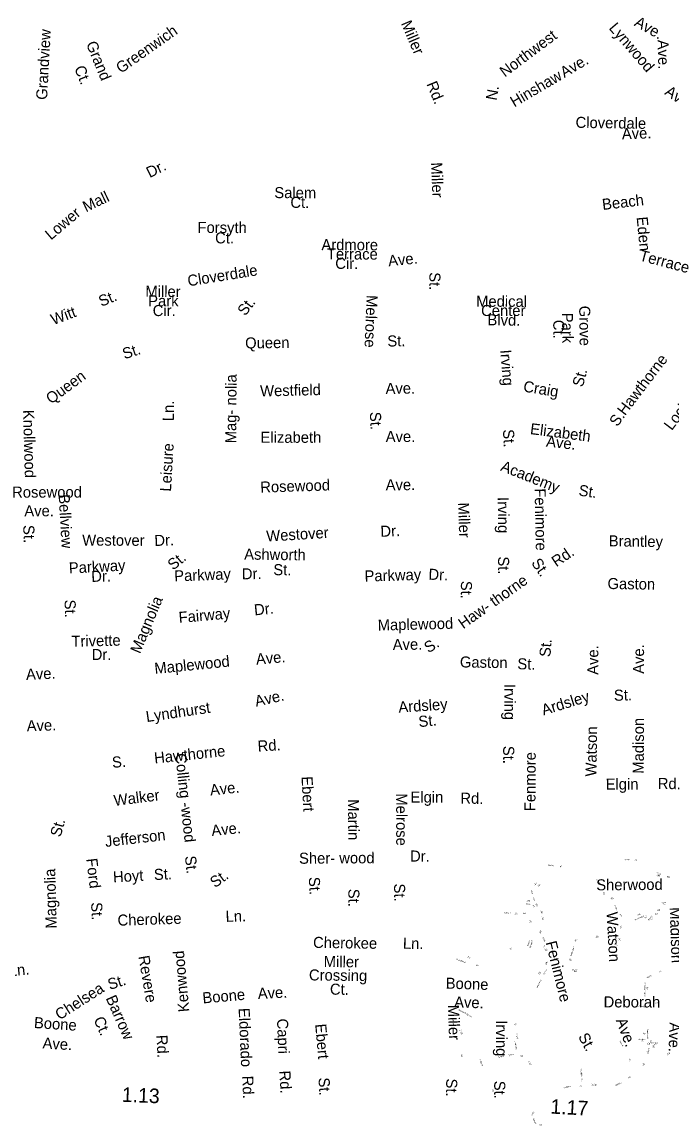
# Model space of a CAD drawing. Extents: x 1553981 to 1780076, y 812965 to 996873.
# Drawn here: x 1620006 to 1625598, y 846729 to 856224 of the extents above; entities that cross this region are included whole.
import ezdxf

# ---------------------------------------------------------------- set-up
doc = ezdxf.new("R2010")
doc.units = 0
for name, color, linetype in [('Exist Road Non-System Type 51 Label', 7, 'Continuous'), ('Exist Road Primary NC Service Mileage Hundredths English Label', 7, 'Continuous'), ('Exist Road Secondary Mileage Hundredths English Label', 7, 'Continuous'), ('Map Preparation Border Antique Large Shape', 7, 'Continuous')]:
    doc.layers.add(name, color=color, linetype=linetype)

msp = doc.modelspace()

# ---------------------------------------------------------------- texts
at = {"layer": 'Exist Road Non-System Type 51 Label'}
for s, height, rotation, p in [('Greenwich', 95, 35.10708, (1620857, 855778.8)), ('Miller', 95, 293.05731, (1623265.4, 856213.3)), ('Lynwood', 95, 310.80779, (1625050.9, 856169.5)), ('Ave.', 95, 330.70891, (1625267.3, 856196.5)), ('Grandview', 95, 86.90435, (1620221.3, 855553.6)), ('Northwest', 95, 36.8499, (1624160.7, 855746.1)), ('Grand', 95, 292.26871, (1620555.3, 856037.4)), ('Ave.', 95, 271.79659, (1625474.2, 856070.7)), ('Ave.', 95, 30.68947, (1624672.3, 855741.7)), ('Ct.', 95, 292.26871, (1620453.7, 855827.4)), ('Rd.', 95, 292.38447, (1623484.6, 855691.5)), ('Hinshaw', 95, 30.38797, (1624241.9, 855489.3)), ('N.', 95, 79.68363, (1624089.3, 855545.4)), ('Ave.', 95, 325.83454, (1625529, 855605.9)), ('Cloverdale', 95, 359.11757, (1624768.8, 855314.4)), ('Ave.', 95, 2.09329, (1625169.2, 855215.2)), ('Dr.', 95, 26.54378, (1621105.3, 854881.2)), ('Miller', 95, 272.09378, (1623526, 855016)), ('Mall', 95, 25.69886, (1620556.5, 854586.8)), ('Salem', 95, 359.76311, (1622177.1, 854709.8)), ('Ct.', 95, 359.76311, (1622315.1, 854625.8)), ('Beach', 95, 6.73645, (1625003.3, 854607.3)), ('Lower', 95, 40.10596, (1620254.4, 854344.2)), ('Forsyth', 95, 359.76311, (1621516.2, 854410.4)), ('Eden', 95, 275.42573, (1625294.4, 854545.6)), ('Ct.', 95, 359.76311, (1621667.2, 854320.3)), ('Ardmore', 95, 359.76311, (1622582.3, 854262)), ('Terrace', 95, 359.76311, (1622629.4, 854182.5)), ('Cir.', 95, 359.76311, (1622701.3, 854101.1)), ('Ave.', 95, 5.53498, (1623160.9, 854123.1)), ('Terrace', 95, 345.23935, (1625311.7, 854174.5)), ('Cloverdale', 95, 9.13157, (1621438.1, 853950.3)), ('St.', 95, 269.36723, (1623511.9, 854072.6)), ('Miller', 95, 359.25494, (1621066.9, 853861.8)), ('St.', 95, 22.14844, (1620688.4, 853774)), ('Park', 95, 359.97373, (1621091.9, 853778.5)), ('St.', 95, 52.13116, (1621925.7, 853690.3)), ('Melrose', 95, 267.67239, (1622971.4, 853877)), ('Medical', 95, 359.87892, (1623913.5, 853775.2)), ('Witt', 95, 20.39681, (1620275.3, 853616.5)), ('Cir.', 95, 0.04818, (1621130.5, 853694.9)), ('Center', 95, 0.0174, (1623956.5, 853695.6)), ('Blvd.', 95, 358.93461, (1624010.7, 853616.4)), ('Park', 95, 270.7268, (1624651.6, 853722.6)), ('Grove', 95, 270.7268, (1624800.2, 853783.7)), ('Ct.', 95, 270.7268, (1624576.5, 853662.4)), ('St.', 95, 1.58406, (1623150.8, 853432.2)), ('St.', 95, 18.38724, (1620888, 853322.3)), ('Queen', 95, 0.76734, (1621926.5, 853415.9)), ('Irving', 95, 274.44308, (1624120.9, 853402.3)), ('Hawthorne', 95, 52.62576, (1625194.5, 852833.3)), ('Queen', 95, 36.1182, (1620255.7, 852934.3)), ('Mag- nolia', 95, 89.70477, (1621849.2, 852600.7)), ('St.', 95, 74.54113, (1624830.9, 853079.5)), ('Lockland', 95, 52.93573, (1625596.8, 852705.3)), ('Westfield', 95, 1.36967, (1622056, 853003.1)), ('Ave.', 95, 0.8492, (1623135, 853024.9)), ('Craig', 95, 350.84398, (1624314.9, 853046.3)), ('Ln.', 95, 89.09124, (1621312.1, 852790.4)), ('Knollwood', 95, 271.55283, (1620014.8, 852887.2)), ('St.', 95, 272.30603, (1622999.2, 852869.3)), ('Elizabeth', 95, 352.6529, (1624374.3, 852680.5)), ('S.', 95, 53.98185, (1625128.5, 852738)), ('Elizabeth', 95, 0.02895, (1622058.6, 852604.7)), ('Ave.', 95, 359.99417, (1623135.7, 852612)), ('St.', 95, 273.23632, (1624143.8, 852719)), ('Leisure', 95, 86.7488, (1621287.9, 852183.3)), ('Ave.', 95, 353.64895, (1624512.8, 852572.9)), ('Academy', 95, 338.24252, (1624116.7, 852367.6)), ('Rosewood', 95, 1.86335, (1622057.5, 852176.1)), ('Ave.', 95, 0.30163, (1623135.5, 852196.5)), ('Rosewood', 95, 0.03651, (1619921, 852133.4)), ('Fenimore', 95, 271.14432, (1624416.8, 852212.4)), ('St.', 95, 351.40585, (1624791, 852152.1)), ('Bellview', 95, 273.29916, (1620320.6, 852159.7)), ('Irving', 95, 270.57413, (1624099.4, 852137.7)), ('Ave.', 95, 0.03651, (1620026, 851972.5)), ('Miller', 95, 272.09378, (1623757.6, 852089.9)), ('St.', 95, 272.29184, (1620015.8, 851896.2)), ('Westover', 95, 359.79414, (1620523.9, 851720.5)), ('Dr.', 95, 2.32272, (1621146.6, 851716.6)), ('Westover', 95, 3.44761, (1622110.8, 851754.8)), ('Dr.', 95, 2.32272, (1623091.7, 851795.7)), ('Brantley', 95, 359.13156, (1625054.3, 851714.6)), ('St.', 95, 39.29161, (1621306.6, 851504.1)), ('Ashworth', 95, 359.24285, (1621917.3, 851600.5)), ('Rd.', 95, 34.12709, (1624603.6, 851533.3)), ('Parkway', 95, 2.96689, (1620411.4, 851480.4)), ('St.', 95, 359.42841, (1622168.1, 851466.5)), ('St.', 95, 270.25788, (1624102.4, 851627.3)), ('St.', 95, 304.92753, (1624384, 851571.3)), ('Dr.', 95, 1.31477, (1620602.8, 851408.2)), ('Parkway', 95, 2.25437, (1621317.5, 851411.9)), ('Dr.', 95, 1.31477, (1621898.6, 851429.5)), ('Parkway', 95, 1.68284, (1622954.6, 851411.2)), ('Dr.', 95, 357.49435, (1623501.8, 851427.8)), ('Haw- thorne', 95, 35.36609, (1623802.6, 851000.1)), ('Gaston', 95, 359.15192, (1625043.7, 851347.4)), ('St.', 95, 269.36723, (1623783.4, 851418.2)), ('St.', 95, 271.95096, (1620371.7, 851254.3)), ('Magnolia', 95, 67.29332, (1621020.7, 850785.3)), ('Fairway', 95, 4.92395, (1621357.7, 851055.2)), ('Dr.', 95, 5.53675, (1622007.2, 851119.9)), ('Maplewood', 95, 1.41936, (1623067.9, 850989.4)), ('Trivette', 95, 1.42146, (1620432.3, 850849.9)), ('Ave.', 95, 0.80337, (1623196.5, 850822.1)), ('S.', 95, 32.67759, (1623504.6, 850792.9)), ('St.', 95, 85.6585, (1624552.1, 850759.9)), ('Dr.', 95, 0.06016, (1620605.7, 850736.5)), ('Maplewood', 95, 5.66663, (1621150.1, 850616.4)), ('Ave.', 95, 4.89719, (1622022.8, 850696.8)), ('Gaston', 95, 359.11848, (1623773.6, 850672.9)), ('Ave.', 95, 89.90593, (1624965, 850609.1)), ('Ave.', 95, 89.93089, (1625358.2, 850618.1)), ('St.', 95, 358.36685, (1624267.5, 850657.5)), ('Ave.', 95, 2.54641, (1620042.2, 850565.4)), ('Irving', 95, 269.9641, (1624157.1, 850530.7)), ('St.', 95, 1.58029, (1625100.5, 850385.4)), ('Ave.', 95, 12.84141, (1622020.6, 850334)), ('Ardsley', 95, 3.756, (1623247.6, 850283.7)), ('Ardsley', 95, 17.19027, (1624493.2, 850259.2)), ('Lyndhurst', 95, 8.36848, (1621078.8, 850202.2)), ('Ave.', 95, 2.03303, (1620047.9, 850122.5)), ('St.', 95, 5.77749, (1623422.4, 850158.7)), ('Madison', 95, 89.75144, (1625355.9, 849758.4)), ('Watson', 95, 89.13617, (1624948.8, 849734)), ('Rd.', 95, 3.86257, (1622036.5, 849947.7)), ('Hawthorne', 95, 6.04226, (1621148.1, 849845.3)), ('Colling -wood', 95, 276.12692, (1621323.9, 849928.8)), ('St.', 95, 269.91602, (1624146.3, 849998.1)), ('Fenmore', 95, 89.66934, (1624423.6, 849436.1)), ('S.', 95, 4.74555, (1620783.7, 849808.7)), ('Ebert', 95, 273.08819, (1622410.6, 849733.9)), ('Rd.', 95, 359.16903, (1625476.1, 849627.7)), ('Ave.', 95, 6.14095, (1621628, 849570.3)), ('Elgin', 95, 0.17749, (1625028.1, 849621.7)), ('Walker', 95, 7.14469, (1620801.5, 849480.6)), ('Melrose', 95, 270.10039, (1623225.4, 849589.6)), ('Elgin', 95, 0.17749, (1623348.9, 849509.7)), ('Rd.', 95, 359.16903, (1623777.3, 849501.4)), ('Martin', 95, 270.55979, (1622810.2, 849538.7)), ('St.', 95, 73.98696, (1620337.2, 849208.5)), ('Jefferson', 95, 6.61791, (1620725.5, 849127.7)), ('Ave.', 95, 5.8705, (1621640, 849222.1)), ('Sher- wood', 95, 0.38056, (1622390, 848983.8)), ('Dr.', 95, 359.1524, (1623344.5, 849003.5)), ('Ford', 95, 276.77281, (1620558.7, 849026.3)), ('St.', 95, 276.10139, (1621407.5, 849048.1)), ('Dalton', 11.88, 355.43839, (1624534.3, 848966.3)), ('Rd.', 11.88, 30.70873, (1624638.5, 848950.2)), ('Dorse', 11.87, 0.76952, (1625189.2, 849011.9)), ('Rd.', 11.88, 349.76445, (1625274.7, 849011.9)), ('Magnolia', 95, 91.49432, (1620305.1, 848427.5)), ('Hoyt', 95, 3.46181, (1620791.8, 848822.2)), ('St.', 95, 2.75591, (1621142.9, 848843.2)), ('St.', 95, 35.97576, (1621666.5, 848772.8)), ('St.', 95, 273.24695, (1622473, 848868.3)), ('St.', 95, 270.49909, (1623207.4, 848813.3)), ('Sherwood', 95, 0.41228, (1624947.4, 848755)), ('St.', 95, 270.21509, (1622814.1, 848768.3)), ('St.', 95, 272.70416, (1620600.1, 848651.2)), ('Madison', 95, 271.93851, (1625579.4, 848608.6)), ('Cherokee', 95, 1.83652, (1620829.6, 848450.6)), ('Ln.', 95, 1.25918, (1621758.7, 848484)), ('Watson', 95, 273.00684, (1625036.3, 848567.5)), ('Cherokee', 95, 359.16342, (1622510.2, 848260.4)), ('Ln.', 95, 359.14638, (1623283.1, 848253)), ('Beech', 11.88, 69.81073, (1624362.8, 848276.6)), ('Valley', 11.88, 67.69773, (1624380.7, 848257.8)), ('Rd.', 11.87, 84.89789, (1624398.7, 848306.4)), ('Fenimore', 95, 283.84401, (1624511.4, 848307.1)), ('Kenwood', 95, 95.01562, (1621445.8, 847712.5)), ('Ln.', 95, 6.08249, (1619897.5, 848014)), ('Revere', 95, 279.59445, (1621006.9, 848186.9)), ('Miller', 95, 359.32304, (1622601.4, 848096)), ('St.', 95, 17.88479, (1620760.9, 847897.6)), ('Crossing', 95, 359.32304, (1622474.6, 847980.5)), ('Chelsea', 95, 32.80654, (1620329.7, 847636.2)), ('Ct.', 95, 359.32304, (1622655.4, 847858)), ('Boone', 95, 358.14501, (1623650.8, 847910.1)), ('Barrow', 95, 293.94283, (1620724.7, 847828)), ('Boone', 95, 5.08444, (1621562.7, 847782.1)), ('Ave.', 95, 2.87609, (1622036.9, 847820.7)), ('Ave.', 95, 358.14501, (1623723.2, 847748.4)), ('Deborah', 95, 359.90324, (1625010.5, 847748.2)), ('Eldorado', 95, 272.48799, (1621869.6, 847741.8)), ('Miller', 95, 272.09378, (1623669.7, 847769.3)), ('Hounds', 11.88, 331.31393, (1623760.4, 847724.9)), ('Greenfield', 11.88, 353.51833, (1625300.6, 847756.3)), ('Dr.', 11.88, 22.98951, (1625459.3, 847779.5)), ('Boone', 95, 356.28469, (1620106.6, 847571.3)), ('Ct.', 95, 293.94283, (1620619.7, 847644.3)), ('Capri', 95, 272.42092, (1622199.6, 847650.2)), ('Ridge', 11.88, 331.31393, (1623813.8, 847695.7)), ('Rd.', 11.88, 331.31393, (1623854, 847673)), ('Ave.', 95, 290.79179, (1625114, 847637.6)), ('Ebert', 95, 275.05888, (1622528.4, 847603.5)), ('Irving', 95, 269.9641, (1624085.8, 847638)), ('Rd.', 11.88, 53.2018, (1624251.5, 847592.1)), ('Ave.', 95, 268.14995, (1625578, 847620.2)), ('Ave.', 95, 356.28469, (1620180.9, 847396.2)), ('Rd.', 95, 272.99577, (1621162.1, 847509.7)), ('Westbend', 11.88, 99.03755, (1624265.3, 847388.6)), ('School', 11.88, 99.03755, (1624276.3, 847476.3)), ('St.', 95, 299.02965, (1624788.8, 847496.8)), ('Rd.', 95, 273.00315, (1622220.3, 847202.9)), ('Woodville', 11.88, 271.15642, (1624813.5, 847221.2)), ('Rd.', 95, 272.12872, (1621900.7, 847158.8)), ('St.', 95, 273.389, (1622556.8, 847142.5)), ('St.', 95, 269.36723, (1623656.4, 847136.7)), ('St.', 95, 269.91602, (1624069.1, 847117.3)), ('Rd.', 11.88, 271.15642, (1624815.2, 847136.9)), ('River', 11.88, 249.30395, (1624403, 846853.9)), ('Bottom', 11.87, 296.08336, (1624400.7, 846790.5)), ('Rd.', 11.88, 9.59105, (1624458.9, 846728.6))]:
    msp.add_text(s, height=height, rotation=rotation, dxfattribs=at).set_placement(p)
at = {"layer": 'Exist Road Primary NC Service Mileage Hundredths English Label'}
for s, rotation, p in [('1.13', 357.55621, (1620862.9, 846936.9)), ('1.17', 356.85887, (1624550.3, 846835.4))]:
    msp.add_text(s, height=125, rotation=rotation, dxfattribs=at).set_placement(p)
at = {"layer": 'Exist Road Secondary Mileage Hundredths English Label'}
for s, height, rotation, p in [('.90', 15, 342.45333, (1625465.5, 848880.6)), ('.44', 15, 39.02492, (1624417.7, 848795)), ('.90', 15, 318.65437, (1625065.3, 848692.9)), ('.23', 15, 357.13626, (1624346.6, 848657.5)), ('.10', 15, 310.31047, (1624419.2, 848637.9)), ('.22', 15, 4.68437, (1625468.8, 848576.9)), ('.59', 15, 359.72451, (1624241.6, 848549.6)), ('.35', 15, 354.20509, (1624362.9, 848482.5)), ('.06', 15, 285.39235, (1624465.6, 848581.2)), ('.05', 15, 277.31115, (1624478.3, 848529.7)), ('.30', 15, 24.87614, (1625302.5, 848534)), ('.17', 15, 49.86697, (1625369.4, 848507.9)), ('.39', 15, 69.66795, (1624467.7, 848378.9)), ('.17', 15, 30.23213, (1625149.8, 848425)), ('.85', 15, 9.44548, (1624940.6, 848347.2)), ('.40', 15, 285.78873, (1625135.3, 848346.6)), ('.77', 15, 31.54455, (1624203.4, 848235.3)), ('.10', 15, 309.27474, (1624498.7, 848253)), ('.17', 15, 7.43529, (1624548.6, 848218)), ('.90', 15, 337.55731, (1623832.7, 848180.3)), ('.32', 15, 354.91586, (1624576, 848161.5)), ('.10', 15, 297.19043, (1624712.5, 848168.9)), ('.56', 15, 62.60703, (1624459.3, 848025.1)), ('.20', 15, 86.26645, (1625392.8, 847896.3)), ('3.16', 15.62, 290.79411, (1623770.6, 847553.1)), ('1.36', 15, 68.9792, (1625167.9, 847573.2)), ('.24', 15, 270.23415, (1625353.7, 847536)), ('.08', 15, 352.95588, (1625382.2, 847430.4)), ('.05', 15, 88.44701, (1625423.9, 847434.5)), ('.25', 15, 291.14424, (1625379.3, 847375.6)), ('.09', 15, 271.2863, (1625431.2, 847428)), ('.43', 15.62, 28.31226, (1625558.3, 847336.3)), ('1.10', 15, 290.94104, (1624362, 847286.8)), ('.25', 15.62, 35.35736, (1625344.2, 847242.6)), ('1.20', 15.62, 349.42261, (1624904.8, 847079.7))]:
    msp.add_text(s, height=height, rotation=rotation, dxfattribs=at).set_placement(p)
at = {"layer": 'Map Preparation Border Antique Large Shape'}
for s, height, rotation, p in [('Dorse', 11.88, 342.45333, (1625461.5, 848902.8)), ('Rd.', 11.88, 356.3217, (1625558, 848865.7)), ('Rd.', 11.87, 55.99146, (1624452.5, 848785.2)), ('Dalton', 11.88, 312.99853, (1624943.9, 848843.5)), ('Path', 11.87, 99.90968, (1624403.7, 848723.7)), ('River', 11.88, 110.74264, (1624421.2, 848665.3)), ('Rd.', 11.88, 286.01325, (1625005, 848738.3)), ('Scott', 11.88, 357.13626, (1624342.2, 848631.5)), ('Rd.', 11.88, 307.50629, (1624395.8, 848624.4)), ('Dalton', 11.88, 294.32778, (1625102, 848624.4)), ('Dorse', 11.87, 359.86858, (1625505.5, 848643)), ('Rd.', 11.88, 359.9592, (1625516.8, 848632)), ('Dinkins', 11.88, 354.57697, (1624157.7, 848558.5)), ('Rd.', 11.87, 0.40866, (1624316.3, 848552)), ('Rd.', 11.88, 321.48771, (1625146, 848543.9)), ('Shallowford', 11.875, 24.87614, (1625281.8, 848493.5)), ('Bantry', 11.88, 50.32711, (1625400.2, 848495)), ('Tr.', 11.88, 48.65516, (1625424.4, 848496.9)), ('Rd.', 11.88, 11.55218, (1625454.5, 848543.6)), ('Scott', 11.87, 291.04608, (1624485, 848349.3)), ('Rd.', 11.88, 54.08843, (1624769.3, 848312.7)), ('Slater', 11.88, 271.95409, (1625111.1, 848363.9)), ('Rd.', 11.88, 259.85597, (1624495, 848285.2)), ('Shallowford', 11.875, 71.7625, (1624733.9, 848187.3)), ('Rd.', 11.88, 276.72922, (1625119.2, 848291.6)), ('Shallowford', 11.875, 340.1011, (1623741.3, 848159.3)), ('Rd.', 11.87, 338.89911, (1623911.3, 848109.6)), ('Rd.', 11.88, 88.4633, (1624524.7, 848117.5)), ('School', 11.87, 64.22264, (1624501.5, 848027.3)), ('Hauser', 11.88, 26.275, (1625380.3, 847996.6)), ('Dr.', 11.88, 30.98769, (1625492.1, 848048.7)), ('Westbend', 11.88, 63.92665, (1624444.1, 847917.2)), ('Sterling Acres Dr.', 11.875, 90, (1625369.3, 847838.6)), ('Williams', 11.88, 275.57843, (1623708.8, 847649.2)), ('Cresthaven', 11.87, 271.36093, (1625383.2, 847562.9)), ('Hauser', 11.88, 299.04401, (1625147.7, 847456.9)), ('Rd.', 11.87, 276.6043, (1625390.3, 847398)), ('Rd.', 11.88, 274.18557, (1623782.9, 847346.9)), ('Williams', 11.88, 289.35691, (1623942.2, 847300.3)), ('Double', 11.88, 15.41504, (1624103.6, 847311.1)), ('Spring', 11.88, 14.90615, (1624190.5, 847328)), ('Rd.', 11.88, 341.69389, (1624293.6, 847329)), ('Dr.', 11.88, 297.50936, (1625226.7, 847303.4)), ('Williams', 11.88, 18.2085, (1624671.1, 847049.1)), ('Rd.', 11.88, 350.57157, (1624801.4, 847070.8)), ('Williams', 11.88, 27.94465, (1625112.3, 847069.8)), ('Rd.', 11.87, 29.75494, (1625224.8, 847136.3)), ('Rd.', 11.88, 288.90079, (1624049, 847043.6))]:
    msp.add_text(s, height=height, rotation=rotation, dxfattribs=at).set_placement(p)
for s, p in [('Strupe', (1624735.9, 848068.1)), ('Rd.', (1624754.7, 848051.9)), ('Ashland', (1625311.9, 847468.1)), ('Ct.', (1625332.8, 847457.7)), ('Ashland', (1625423.6, 847435.1)), ('Ct.', (1625444.4, 847425.1))]:
    msp.add_text(s, height=11.88, dxfattribs=at).set_placement(p)

doc.saveas('drawing.dxf')
